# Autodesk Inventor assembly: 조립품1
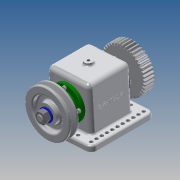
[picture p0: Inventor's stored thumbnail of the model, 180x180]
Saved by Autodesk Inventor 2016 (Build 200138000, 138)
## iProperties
Created: 2018-11
Part Number: 조립품1
Document SubType Name: Assembly
Designer: Administrator
Author: Administrator
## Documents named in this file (13)
- Y:\481107V1004 홍진욱\481107V1004\조립품1.iam
- Y:\481107V1004 홍진욱\481107V1004\V벨트풀리.ipt
- Y:\481107V1004 홍진욱\481107V1004\너트 M12x1.25.ipt
- Y:\481107V1004 홍진욱\481107V1004\베어링 6203.ipt
- Y:\481107V1004 홍진욱\481107V1004\볼트 M4.ipt
- Y:\481107V1004 홍진욱\481107V1004\부시.ipt
- Y:\481107V1004 홍진욱\481107V1004\부품1.ipt
- Y:\481107V1004 홍진욱\481107V1004\스퍼기어.ipt
- Y:\481107V1004 홍진욱\481107V1004\오일 실 26 38 8.ipt
- Y:\481107V1004 홍진욱\481107V1004\와셔 12x24.ipt
- Y:\481107V1004 홍진욱\481107V1004\축.ipt
- Y:\481107V1004 홍진욱\481107V1004\커버.ipt
- Y:\481107V1004 홍진욱\481107V1004\키 5x5x12.ipt
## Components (1 placed, 1 different names)
1. V벨트풀리:1
